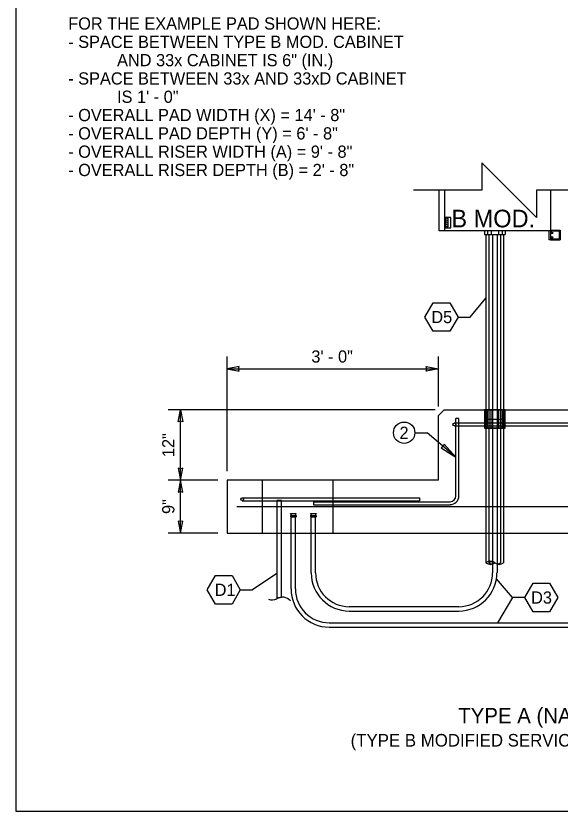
# Model space of a CAD drawing. Extents: x 99862 to 103151, y 100000 to 117076.
# Drawn here: x 99862 to 100575, y 112000 to 113042 of the extents above; entities that cross this region are included whole.
import ezdxf

# ---------------------------------------------------------------- set-up
doc = ezdxf.new("R2010")
doc.units = 0
for name, color, linetype in [('Default', 7, 'Continuous'), ('Level 1', 7, 'Continuous'), ('Level 11', 7, 'Continuous'), ('Level 15', 7, 'Continuous'), ('Level 20', 7, 'Continuous'), ('Level 40', 7, 'Continuous'), ('Level 6', 7, 'Continuous'), ('Level 60', 7, 'Continuous')]:
    doc.layers.add(name, color=color, linetype=linetype)

msp = doc.modelspace()

# ---------------------------------------------------------------- linework, layer by layer
at = {"layer": 'Default'}
for p, q in [((100436.9, 112508.3), (101306.5, 112508.3)), ((100436.9, 112504.5), (101306.5, 112504.5)), ((100438.9, 112412.8), (100438.9, 112514.1)), ((100442.7, 112514.1), (100438.9, 112514.1)), ((100442.7, 112412.8), (100442.7, 112514.1)), ((100158.6, 112410.3), (100391.1, 112410.3)), ((100158.6, 112406.4), (100391.1, 112406.4)), ((100252.3, 112405.1), (100252.3, 112401.2)), ((100252.3, 112405.1), (100431.2, 112405.1)), ((100252.3, 112401.2), (100431.2, 112401.2)), ((100391.1, 112410.3), (100391.1, 112406.4))]:
    msp.add_line(p, q, dxfattribs=at)
for centre in [(100436.9, 112506.4), (100158.6, 112408.4)]:
    msp.add_circle(centre, 1.92, dxfattribs=at)
for radius in [11.5, 7.7]:
    msp.add_arc((100431.2, 112412.8), radius, 270, 0, dxfattribs=at)
at = {"layer": 'Level 1'}
for p, q in [((100424.4, 112777.7), (100424.4, 112764.1)), ((100425.1, 112776.2), (100425.1, 112765.6)), ((100428.2, 112776.2), (100425.1, 112775)), ((100428.2, 112776.2), (100428.2, 112765.6)), ((100428.2, 112773.7), (100425.1, 112772.5)), ((100428.2, 112771.2), (100425.1, 112770.1)), ((100428.2, 112768.8), (100425.1, 112767.6)), ((100428.2, 112766.3), (100425.2, 112765.1)), ((100476.3, 112760.2), (100476.3, 112755.6)), ((100476.3, 112755.6), (100503.3, 112755.6)), ((100478.2, 112755.6), (100478.2, 112525.4)), ((100480.2, 112760.2), (100480.2, 112755.6)), ((100480.2, 112755.6), (100499.4, 112755.6)), ((100482.1, 112755.6), (100482.1, 112525.4)), ((100485, 112760.2), (100485, 112755.6)), ((100485, 112755.6), (100494.6, 112755.6)), ((100486.9, 112755.6), (100486.9, 112525.4)), ((100492.7, 112755.6), (100492.7, 112525.4)), ((100494.6, 112760.2), (100494.6, 112755.6)), ((100497.5, 112755.6), (100497.5, 112525.4)), ((100499.4, 112760.2), (100499.4, 112755.6)), ((100501.3, 112755.6), (100501.3, 112525.4)), ((100503.3, 112760.2), (100503.3, 112755.6)), ((100478.2, 112525.4), (100478.2, 112325)), ((100482.1, 112525.4), (100482.1, 112325)), ((100486.9, 112525.4), (100486.9, 112311.8)), ((100492.7, 112525.4), (100492.7, 112311.8)), ((100497.5, 112525.4), (100497.5, 112325)), ((100501.3, 112525.4), (100501.3, 112325)), ((100478.2, 112513.5), (100501.3, 112513.5)), ((100222, 112389.5), (100229.2, 112389.5)), ((100222, 112387.1), (100222, 112385.4)), ((100222, 112387.1), (100229.2, 112387.1)), ((100222, 112385.4), (100229.2, 112385.4)), ((100222.7, 112387.8), (100222.7, 112387.1)), ((100222.7, 112290.7), (100222.7, 112385.4)), ((100228.4, 112387.8), (100228.4, 112387.1)), ((100228.4, 112290.7), (100228.4, 112385.4)), ((100229.2, 112387.1), (100229.2, 112385.4)), ((100248.3, 112389.5), (100255.5, 112389.5)), ((100248.3, 112387.1), (100248.3, 112385.4)), ((100248.3, 112387.1), (100255.5, 112387.1)), ((100248.3, 112385.4), (100255.5, 112385.4)), ((100249, 112387.8), (100249, 112387.1)), ((100249, 112311.8), (100249, 112385.4)), ((100254.8, 112387.8), (100254.8, 112387.1)), ((100254.8, 112311.8), (100254.8, 112385.4)), ((100255.5, 112387.1), (100255.5, 112385.4)), ((100299.1, 112267.6), (100442.6, 112267.6)), ((100299.1, 112261.8), (100442.6, 112261.8)), ((100272.7, 112246.4), (101356.5, 112246.4)), ((100272.7, 112240.7), (101356.5, 112240.7))]:
    msp.add_line(p, q, dxfattribs=at)
for points in [[(99862, 111999.5), (103151, 111999.5), (103151, 114075.5), (99862, 114075.5)], [(100476.3, 112501.6), (100503.3, 112501.6), (100503.3, 112525.4), (100476.3, 112525.4)], [(100499.4, 112501.6), (100480.2, 112501.6), (100480.2, 112525.4), (100499.4, 112525.4)], [(100485, 112525.4), (100494.6, 112525.4), (100494.6, 112501.6), (100485, 112501.6)], [(100204.1, 112406.5), (100204.1, 112278), (100206.3, 112279.1), (100208.3, 112279.6), (100210.4, 112280), (100210.4, 112406.5)]]:
    msp.add_lwpolyline(points, close=True, dxfattribs=at)
msp.add_lwpolyline([(100424.4, 112764.1), (100432.1, 112764.1), (100432.1, 112777.7), (100424.4, 112777.7)], dxfattribs=at)
for centre, radius, start, end in [((100426.7, 112776.2), 1.54, 90, 180), ((100426.7, 112776.2), 1.54, 0, 90), ((100426.7, 112765.6), 1.54, 180, 270), ((100426.7, 112765.6), 1.54, 270, 0), ((100220.3, 112387.8), 2.37, 0, 45.9402), ((100230.8, 112387.8), 2.37, 134.0598, 180), ((100246.7, 112387.8), 2.37, 0, 45.9402), ((100257.2, 112387.8), 2.37, 134.0598, 180), ((100484, 112318), 9.14, 50.8329, 129.1671), ((100484, 112332.1), 9.14, 230.8329, 309.1671), ((100485.9, 112320.3), 6.09, 50.8329, 129.1671), ((100485.9, 112329.8), 6.09, 230.8329, 309.1671), ((100495.6, 112332.1), 9.14, 230.8329, 309.1671), ((100493.6, 112329.8), 6.09, 230.8329, 309.1671), ((100299.1, 112311.8), 50, 180, 270), ((100299.1, 112311.8), 44.3, 180, 270), ((100442.6, 112311.8), 44.3, 270, 0), ((100442.6, 112311.8), 50, 270, 0), ((100272.7, 112290.7), 50, 180, 270), ((100272.7, 112290.7), 44.3, 180, 270), ((100197.8, 112291.1), 14.6, 250.7571, 295.3506), ((100211.4, 112265.8), 14.1, 42.3778, 121.1813)]:
    msp.add_arc(centre, radius, start, end, dxfattribs=at)
at = {"layer": 'Level 11'}
for p, q in [((100184.9, 112433.3), (100184.9, 112364)), ((100277.3, 112433.3), (100277.3, 112364))]:
    msp.add_line(p, q, dxfattribs=at)
for points in [[(100415.8, 112433.3), (100415.8, 112517.9), (100423.5, 112525.6)], [(100423.5, 112525.6), (101319.9, 112525.6)], [(100415.8, 112433.3), (100138.8, 112433.3)], [(100138.8, 112433.3), (100138.8, 112364)], [(100138.8, 112364), (101512.3, 112364)]]:
    msp.add_lwpolyline(points, dxfattribs=at)
at = {"layer": 'Level 15'}
for p, q in [((100424.4, 112760.2), (100424.4, 112813.6)), ((100561, 112748.6), (100561, 112760.2)), ((100562.9, 112748.6), (100561, 112748.6)), ((100457.6, 112647.2), (100478.2, 112671.8)), ((100441.6, 112647.2), (100457.6, 112647.2)), ((100138.8, 112445.3), (100138.8, 112595.5)), ((100415.8, 112529.9), (100415.8, 112595.5)), ((100138.8, 112579.5), (100415.8, 112579.5)), ((100411.5, 112525.6), (100061.8, 112525.6)), ((100077.8, 112433.3), (100077.8, 112525.6)), ((100385, 112495.5), (100401, 112495.5)), ((100438.9, 112463.4), (100401, 112495.5)), ((100126.8, 112433.3), (100061.8, 112433.3)), ((100077.8, 112364), (100077.8, 112433.3)), ((100126.8, 112364), (100061.8, 112364)), ((100204.1, 112311.1), (100172.1, 112289.6)), ((100513.2, 112279.5), (100492, 112303.9)), ((100156.1, 112289.6), (100172.1, 112289.6)), ((100513.2, 112279.5), (100493.2, 112246.4)), ((100529.2, 112279.5), (100513.2, 112279.5))]:
    msp.add_line(p, q, dxfattribs=at)
msp.add_lwpolyline([(100622.2, 112813.6), (100544.5, 112813.6), (100544.5, 112777.7), (100472.7, 112849.5), (100472.7, 112813.6), (100383.4, 112813.6)], dxfattribs=at)
for points in [[(100138.8, 112579.5), (100154.5, 112576.4), (100153.7, 112579.5), (100154.5, 112582.5)], [(100415.8, 112579.5), (100400, 112576.4), (100400.8, 112579.5), (100400, 112582.5)], [(100077.8, 112525.6), (100080.9, 112509.9), (100077.8, 112510.6), (100074.7, 112509.9)], [(100438.9, 112463.4), (100423.4, 112480.5), (100422.2, 112477.5), (100419.5, 112475.9)], [(100077.8, 112433.3), (100080.9, 112449), (100077.8, 112448.3), (100074.7, 112449)], [(100077.8, 112433.3), (100074.7, 112417.6), (100077.8, 112418.3), (100080.9, 112417.6)], [(100077.8, 112364), (100080.9, 112379.8), (100077.8, 112379), (100074.7, 112379.8)]]:
    msp.add_lwpolyline(points, close=True, dxfattribs=at)
at = {"layer": 'Level 20'}
for points in [[(100398.3, 112647.2), (100409.2, 112666), (100430.8, 112666), (100441.6, 112647.2), (100430.8, 112628.5), (100409.2, 112628.5), (100398.3, 112647.2)], [(100112.8, 112289.6), (100123.7, 112308.4), (100145.3, 112308.4), (100156.1, 112289.6), (100145.3, 112270.9), (100123.7, 112270.9), (100112.8, 112289.6)], [(100529.2, 112279.5), (100540, 112298.2), (100561.7, 112298.2), (100572.5, 112279.5), (100561.7, 112260.7), (100540, 112260.7), (100529.2, 112279.5)]]:
    msp.add_lwpolyline(points, dxfattribs=at)
msp.add_circle((100371, 112495.5), 14, dxfattribs=at)
at = {"layer": 'Level 40'}
for p, q in [((100416.7, 112760.2), (100416.7, 112813.6)), ((100562.9, 112813.6), (100562.9, 112748.6)), ((100562.9, 112760.2), (100416.7, 112760.2)), ((100562.9, 112761.1), (100575.4, 112761.1)), ((100562.9, 112761.1), (100562.9, 112757.3)), ((100562.9, 112757.3), (100565.9, 112757.3)), ((100563.9, 112760.2), (100574.4, 112760.2)), ((100563.9, 112760.2), (100563.9, 112758.2)), ((100563.9, 112758.2), (100565.9, 112758.2)), ((100565.9, 112758.2), (100565.9, 112757.3)), ((100574.4, 112760.2), (100574.4, 112749.6)), ((100575.4, 112761.1), (100575.4, 112748.6)), ((100562.9, 112752.4), (100565.9, 112752.4)), ((100562.9, 112752.4), (100562.9, 112748.6)), ((100562.9, 112748.6), (100575.4, 112748.6)), ((100563.9, 112751.5), (100565.9, 112751.5)), ((100563.9, 112751.5), (100563.9, 112749.6)), ((100563.9, 112749.6), (100574.4, 112749.6)), ((100565.9, 112752.4), (100565.9, 112751.5)), ((100151.6, 112398.7), (101499.5, 112398.7))]:
    msp.add_line(p, q, dxfattribs=at)
at = {"layer": 'Level 60'}
msp.add_line((99862, 111999.5), (99862, 111999.5), dxfattribs=at)

# ---------------------------------------------------------------- texts
at = {"layer": 'Level 20'}
for s, height, p in [('FOR THE EXAMPLE PAD SHOWN HERE:', 16, (99930.6, 113024)), ('- SPACE BETWEEN TYPE B MOD. CABINET', 16, (99930.6, 113000)), ('AND 33x CABINET IS 6" (IN.)', 16, (99994.6, 112976)), ('- SPACE BETWEEN 33x AND 33xD CABINET', 16, (99930.6, 112952)), ('IS 1\' - 0"', 16, (99994.6, 112928)), ('- OVERALL PAD WIDTH (X) = 14\' - 8"', 16, (99930.6, 112904)), ('- OVERALL PAD DEPTH (Y) = 6\' - 8"', 16, (99930.6, 112880)), ('- OVERALL RISER WIDTH (A) = 9\' - 8"', 16, (99930.6, 112856)), ('- OVERALL RISER DEPTH (B) = 2\' - 8"', 16, (99930.6, 112832)), ('D5', 16, (100406.6, 112639.2)), ('3\' - 0"', 16, (100249.3, 112587.5)), ('2', 16, (100364.9, 112487.5)), ('D1', 16, (100122.6, 112281.6)), ('D3', 16, (100537.4, 112271.5)), ('TYPE A (NARROW) MULTI-CABINET FOUNDATION PAD', 20, (100441.9, 112114.7)), ('(TYPE B MODIFIED SERVICE CABINET, TYPE 33x CABINET, AND TYPE 33xD CABINET SHOWN)', 16.5, (100300.8, 112084.1))]:
    msp.add_text(s, height=height, dxfattribs=at).set_placement(p)
for s, p in [('12"', (100069.8, 112463.6)), ('9"', (100069.8, 112389))]:
    msp.add_text(s, height=16, rotation=90, dxfattribs=at).set_placement(p)
at = {"layer": 'Level 6'}
msp.add_text('B MOD.', height=23.09, dxfattribs=at).set_placement((100432.9, 112764.8))

doc.saveas('drawing.dxf')
